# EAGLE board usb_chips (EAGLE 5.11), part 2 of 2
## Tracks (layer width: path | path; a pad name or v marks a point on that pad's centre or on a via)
3.3V  (via drill 0.6)
  Top 0.178: 52.92,24.64 TRANS3.12 52.95,24.64 53.47,24.64 53.72,24.38 53.72,23.75 v53.21,23.24 53.59,22.86 53.59,21.72 52.96,21.08 51.94,21.08 51.43,21.59 | PERIPH_XVER.12 39.61,24.65 40,24.26 40,23.11 39.5,22.61 v38.61,22.61 37.72,22.61 | JP12.2 46.48,23.11 49.15,23.11 49.53,22.73 49.53,21.59 50.04,21.08 50.93,21.08 51.43,21.59 | HOST1_CTL.P$23 48.37,40.41 48.39,40.39 48.39,40.13 v48.89,39.62 | 48.39,46.26 HOST1_CTL.P$2 48.37,47.35 48.51,47.5 v48.54,47.5 | v43.81,34.54 44.07,34.29 CLOSE_TO_PINS-2.2.2 | v34.04,22.61 35.05,21.59 36.96,21.59 37.72,22.35 37.72,22.61 | v27.69,23.37 26.42,24.64 26.02,24.64 HOST_XVER.12 | v22.86,22.35 23.75,21.46 24.51,21.46 24.89,21.84 24.89,23.11 24.77,23.24 HOST_XVER.14 | v28.96,50.42 28.45,49.91 25.53,49.91 24.77,50.67 24.77,52.71 24.38,53.09 23.62,53.09 23.5,52.96 22.61,52.96 21.84,53.72 21.84,55.37 22.1,55.63 22.48,55.63 22.99,56.13 22.99,56.9 22.35,57.53 21.84,57.53 21.08,56.77 21.08,53.09 v20.21,52.21 v20.19,52.21 20.08,52.21 19.81,52.48 18.31,52.48 17.78,51.94 17.78,48.51 18.41,47.88 18.41,47.37 17.65,46.61 17.65,45.21 17.14,44.7 16.76,44.7 16.38,44.32 14.48,44.32 13.59,45.21 13.59,46.99 15.49,48.9 v15.49,55.88 | PERIPH1_CTL.P$23 31.1,45.19 v31.62,45.72 32,46.1 34.8,46.1 v35.69,46.99 | 37.72,22.61 PERIPH_XVER.14 | 51.43,21.59 51.69,21.84 TRANS3.14 | v25.02,45.34 25.17,45.19 PERIPH1_CTL.P$2
  Bottom 0.178: 30.35,24.64 29.85,24.13 29.08,24.13 28.32,23.37 v27.69,23.37 27.69,22.99 26.92,22.22 24.89,22.22 24.51,21.84 23.37,21.84 v22.86,22.35 | 30.35,24.64 JP11.2 | 30.35,24.64 30.86,24.13 31.24,24.13 32.77,22.61 v34.04,22.61 | 15.37,64.35 C2.2 13.34,66.67 3.3V_REF.1 | 15.37,64.35 R14.1 | 14.35,56.39 14.86,56.9 14.86,60.58 16.51,62.23 16.51,63.21 15.37,64.35 | 14.87,55.87 14.35,56.39 | v25.02,45.34 22.99,47.37 22.99,51.69 22.1,52.58 20.57,52.58 v20.21,52.21 v20.19,52.21 | v15.49,55.88 15.48,55.87 14.87,55.87 | v28.96,50.42 29.85,49.53 29.85,47.5 v31.62,45.72 | v35.69,46.99 CLOSE_TO_PINS-1.1.2 CLOSE_TO_PINS-1.2.2 37.76,45.21 46.48,45.21 46.95,45.68 CLOSE_TO_PINS-2.1.2 48.39,46.74 | 48.39,46.74 48.39,40.13 v48.89,39.62 47.88,39.62 46.61,38.35 46.61,36.58 45.34,35.31 44.58,35.31 v43.81,34.54 46.74,31.62 46.74,27.94 JP12.2 44.2,24.51 43.81,24.13 42.8,24.13 41.91,23.24 40.13,23.24 39.5,22.61 v38.61,22.61 | 48.39,46.74 48.39,47.37 48.51,47.5 v48.54,47.5 | JP13.2 55.37,25.4 v53.21,23.24 | 14.35,56.39 14.3,56.44 3.3V_TOPROC.2 | 14.87,55.87 14.82,55.82 5V->3.3V.VOUT
5V  (via drill 0.6)
  Top 0.178: v44.58,15.49 43.81,16.26 42.8,16.26 42.42,16.64 41.15,16.64 40.89,16.89 v40.89,17.53 39.62,17.53 38.61,16.51 38.61,16 38.99,15.62 C13.2 | 5V_TOPROC.2 14.1,59.94 14.86,59.18 14.86,58.42 15.37,57.91 18.41,57.91 | 18.41,57.91 19.3,57.91 20.32,58.93 20.32,59.05 21.08,59.82 21.72,59.82 21.84,59.69 22.86,59.69 23.11,59.94 23.88,59.94 24.13,59.69 25.53,59.69 26.04,60.2 26.04,61.21 26.29,61.47 HOST1_VBUS.3 | v20.7,5.59 19.94,6.35 17.65,6.35 17.4,6.1 16.22,6.1 R1.2 | v16.26,13.84 16.26,9.53 15.75,9.02 15.75,7.37 16.13,6.98 R1.2 | R1.2 15.2,6.18 14.86,5.84 14.86,4.32 v14.35,3.81 | v8.51,42.16 7.49,43.18 3.05,43.18 1.4,41.53 1.4,6.35 v2.67,5.08 | v28.07,6.1 28.19,6.22 30.35,6.22 30.73,6.6 32.89,6.6 33.91,5.59 33.91,3.94 34.29,3.56 34.54,3.56 v35.18,2.92 | v46.61,6.35 46.99,6.73 48.89,6.73 49.4,6.22 50.67,6.22 v51.18,5.71 | HOST2_VBUS.3 37.46,59.82 37.72,59.56 38.35,59.56 38.99,58.93 41.4,58.93 v42.16,58.17 | v8,60.96 8.51,60.45 8.51,56.9 9.52,55.88 9.52,54.1 11.25,52.38 v11.35,52.38 | v14.86,65.15 10.41,65.15 v9.78,65.79 9.52,66.04 7.49,66.04 5V_SOURCE.1 | 18.41,57.91 16.51,56.01 16.51,55.25 15.88,54.61 15.88,48.77 14.86,47.75 v14.86,45.21
  Bottom 0.178: R2.2 27.73,6.44 v28.07,6.1 26.8,6.1 25.78,5.08 25.78,3.81 25.27,3.3 24.26,3.3 23.75,3.81 23.75,4.57 22.73,5.59 v20.7,5.59 | AP2146_3/4.IN 44.58,13.94 v44.58,15.49 45.08,16 45.34,16 46.1,16.76 46.86,16.76 47.24,16.38 48.13,16.38 49.28,17.53 50.04,17.53 50.55,17.02 50.55,16.26 50.29,16 50.29,9.4 50.67,9.02 50.67,6.22 v51.18,5.71 | C14.2 40.55,19.9 40.89,19.56 v40.89,17.53 | R4.2 47.88,7.62 v46.61,6.35 46.1,5.84 46.1,4.06 45.85,3.81 45.85,2.92 44.83,1.91 36.2,1.91 v35.18,2.92 35.18,3.3 35.94,4.06 35.94,4.95 37.08,6.1 37.59,6.1 37.85,6.35 37.85,7.4 R3.2 | AP2146_1/2.IN 15.24,21.55 C12.2 C11.2 15.02,18.38 15.11,18.29 15.62,18.29 16.64,17.27 17.91,17.27 19.05,16.13 19.05,14.86 18.03,13.84 v16.26,13.84 | v14.35,3.81 13.08,3.81 11.81,5.08 v2.67,5.08 | HOST1_VBUS.3 29.97,61.47 31.75,63.25 35.56,63.25 36.2,62.61 36.2,61.85 36.58,61.47 HOST2_VBUS.3 | v42.16,58.17 44.7,58.17 46.35,59.82 46.35,61.09 46.74,61.47 HOST3_VBUS.3 49.53,61.47 51.56,59.44 55.63,59.44 56.52,60.33 56.52,61.21 56.77,61.47 HOST4_VBUS.3 | R13.1 17.36,68.8 17.02,68.45 17.02,65.79 16.38,65.15 v14.86,65.15 | v9.78,65.79 10.29,65.79 10.79,65.28 C1.2 9.61,64.35 9.27,64.01 9.27,61.34 8.89,60.96 v8,60.96 8.51,60.45 8.51,58.67 9.02,58.17 12.32,58.17 13.34,59.18 5V_TOPROC.2 | 5V->3.3V.VIN 10.29,53.78 10.29,52.58 10.49,52.38 v11.35,52.38 | v8.51,42.16 11.81,42.16 v14.86,45.21
-RES1  (via drill 0.6)
  Top 0.178: PROC_INTERFACE.11 8.38,52.07 8.76,51.69 8.76,49.66 9.27,49.15 9.91,49.15 v10.16,48.9 | v30.89,37.62 30.84,37.62 28.07,40.39 PERIPH1_CTL.P$12
  Bottom 0.178: v10.16,48.9 10.54,49.28 15.11,49.28 17.91,52.07 17.91,53.72 18.29,54.1 19.05,54.1 19.69,53.47 22.35,53.47 22.73,53.09 24.38,53.09 24.77,52.71 24.77,47.88 26.8,45.85 26.8,43.05 28.83,41.02 28.83,40.13 30.48,38.48 30.48,38.02 v30.89,37.62
-RES2  (via drill 0.6)
  Top 0.178: HOST1_CTL.P$12 43.82,44.19 39.12,48.9 37.97,48.9 36.96,49.91 36.96,50.8 37.34,51.18 38.86,51.18 40.13,52.45 41.27,52.45 41.78,52.96 41.78,54.36 42.42,54.99 43.94,54.99 44.32,55.37 44.32,58.04 42.8,59.56 41.91,59.56 40.39,61.09 40.39,62.23 40.13,62.48 40.13,63.25 40.39,63.5 40.39,65.15 40.77,65.53 40.77,68.33 v40.13,68.96
  Bottom 0.178: PROC_INTERFACE.12 2.92,53.59 2.92,69.09 3.81,69.98 39.62,69.98 40.13,69.47 v40.13,68.96
-SS1  (via drill 0.6)
  Top 0.178: PERIPH1_CTL.P$14 29.07,40.91 31.24,38.74 32.13,38.74 32.38,38.48 32.77,38.48 33.02,38.23 v33.4,38.23
  Bottom 0.178: PROC_INTERFACE.9 8.25,53.34 8.25,52.45 10.67,50.04 14.86,50.04 17.14,52.32 17.14,53.98 18.03,54.86 19.3,54.86 19.94,54.23 22.61,54.23 22.99,53.85 24.64,53.85 25.53,52.96 25.53,48.13 27.56,46.1 27.56,43.31 29.59,41.28 29.59,40.39 31.24,38.74 32.13,38.74 32.38,38.48 33.15,38.48 v33.4,38.23
-SS2  (via drill 0.6)
  Top 0.178: HOST1_CTL.P$14 43.68,43.19 38.73,48.13 37.72,48.13 36.2,49.66 36.2,51.05 37.08,51.94 38.35,51.94 38.73,52.32 38.73,54.36 39.37,54.99 39.37,56.52 v40.89,58.04 | v41.02,62.87 42.16,64.01 v42.93,64.01
  Bottom 0.178: PROC_INTERFACE.14 2.54,51.44 2.54,69.21 3.68,70.36 40.39,70.36 41.02,69.72 41.02,68.33 40.77,68.07 40.77,64.64 41.4,64.01 v42.93,64.01 | v40.89,58.04 40.89,62.74 v41.02,62.87
GND  (via drill 0.6)
  Top 0.178: 18.41,64.77 3.3V_STATUS.C 17.94,64.55 16.38,62.99 | 18.41,64.77 19.43,64.77 v19.94,65.28 | v29.85,65.28 29.85,65.02 29.21,64.39 26.67,64.39 26.04,65.02 26.04,65.72 HOST1.GND | HOST2.GND 36.2,65.72 36.2,65.02 36.96,64.26 37.85,64.26 37.97,64.39 38.99,64.39 39.62,65.02 | v50.16,65.79 50.16,64.64 49.78,64.26 47.12,64.26 46.35,65.02 46.35,65.72 HOST3.GND | HOST4.GND 56.54,64.74 57.28,64.01 59.31,64.01 v59.56,64.26 | v18.16,8.64 18.25,8.64 PERIPH1_STATUS.C 19.56,9.27 19.81,9.02 19.84,9.04 v20.78,9.04 | TRANS3.PAD 51.18,25.65 TRANS3.6 51.18,27.94 v50.67,28.45 | C18.1 C19.1 53.38,40.13 52.45,40.13 51.94,39.62 v51.18,39.62 | v50.16,37.59 49.06,36.49 C20.1 48.39,35.47 CLOSE_TO_PINS-2.2.1 47.2,33.36 | HOST1_CTL.P$3 47.87,44.69 HOST1_CTL.P$33 46.37,43.19 HOST1_CTL.P$19 46.37,40.65 45.72,40.01 v44.7,40.01 | HOST1_CTL.P$3 47.88,46.25 | 47.2,33.36 46.86,33.02 44.07,33.02 40.89,36.2 v40.89,37.34 | GND_TOPROC.2 18.16,59.69 17.65,60.2 17.65,60.96 17.14,61.47 17.14,62.23 16.38,62.99 | 16.38,62.99 v15.62,62.99 | v16.26,57.02 15.24,57.02 14.48,56.26 14.48,54.74 13.84,54.1 v13.84,52.38 13.84,48.13 13.34,47.62 v10.16,47.62 | 31.37,53.09 C16.1 | 31.37,53.09 C17.1 | PERIPH1_CTL.P$3 27.57,44.69 PERIPH1_CTL.P$33 29.07,43.19 PERIPH1_CTL.P$19 32.12,43.19 v32.38,42.93 | HOST_XVER.PAD 24.26,25.65 HOST_XVER.6 24.26,28.09 v24.49,28.32 | v36.83,19.68 37.21,20.07 46.61,20.07 v48.64,22.1 | PERIPH_XVER.PAD 37.21,25.65 PERIPH_XVER.6 37.21,27.94 v37.59,28.32 | v16.64,7.75 16.64,12.47 v17.14,12.98 | v21.59,22.35 21.08,21.84 20.19,21.84 19.43,22.61 19.18,22.61 17.65,21.08 17.65,20.45 v18.29,19.81
  Top 0.178: v47.62,24.13 45.08,26.67 42.04,26.67 v41.91,26.8 | 5V_STATUS.C 17.56,68.99 17.02,68.45 | 17.02,68.45 17.02,66.17 18.41,64.77 | 17.02,68.45 16.51,67.94 3.3V_REF.2 12.7,66.04 11.05,66.04 9.14,67.94 5V_SOURCE.2 | v31.37,51.56 31.37,53.09 | HOST1_CTL.P$3 47.87,46.62 47.75,46.74 47.75,47.62 47.37,48.01 v47.37,48.64 | PERIPH3_STATUS.C 40.13,12.06 40.51,12.45 40.51,13.46 | v40.51,13.59 40.51,13.46 | 40.51,13.46 40.17,13.12 C13.1 | v37.46,15.75 34.92,13.21 PERIPH2.GND | 46.48,17.27 46.48,18.29 46.1,18.67 42.54,18.67 v42.04,18.16 | 46.48,17.27 v46.48,15.88 | C10.1 56.01,12.79 56.01,11.81 55.75,11.56 55.5,11.56 55.18,11.24 PERIPH4.GND | PERIPH3.GND 46.73,8.89 47.37,8.89 48.93,7.33 PERIPH4_STATUS.C | 46.48,17.27 v47.75,17.27 | PERIPH1.GND 24.77,12.19 27.18,14.61 28.7,14.61 29.08,14.22 | 29.08,14.22 29.08,12.99 C5.1 29.21,12.87 29.21,11.94 29.72,11.43 PERIPH2_STATUS.C | 29.08,14.22 29.59,14.22 v29.95,14.58 | 39.62,65.02 39.62,63.75 39.37,63.5 39.37,62.23 39.62,61.98 39.62,60.35 v39.22,59.94 | 39.62,65.02 39.62,66.06 v39.6,66.09 | 47.2,33.36 47.85,32.72 v48.08,32.72
  Bottom 0.178: v15.62,62.99 15.28,62.65 C2.1 C1.1 | v19.94,65.28 21.72,67.06 28.07,67.06 v29.85,65.28 31.62,67.06 38.63,67.06 v39.6,66.09 39.62,66.06 39.62,65.28 41.27,63.63 41.91,63.63 42.29,63.25 42.8,63.25 42.93,63.12 43.81,63.12 44.58,63.88 48.26,63.88 v50.16,65.79 51.43,67.06 58.55,67.06 59.82,65.79 59.82,64.52 v59.56,64.26 | C3.1 17.57,9.23 v18.16,8.64 19.69,7.11 C4.1 | C7.1 42.54,8.64 43.18,8.64 PERIPH3.GND 45.08,13.59 45.31,13.81 AP2146_3/4.GND 45.72,15.11 v46.48,15.88 | v50.16,37.59 50.16,38.61 v51.18,39.62 | CLOSE_TO_PINS-2.1.1 45.25,48.17 45.72,48.64 v47.37,48.64 | 5V->3.3V.GND 13.34,53.85 13.84,53.34 v13.84,52.38 | v16.26,57.02 16.76,57.02 17.65,57.91 17.65,59.18 18.16,59.69 GND_TOPROC.2 | AP2146_1/2.GND 16.51,21.55 C12.1 | C12.1 C11.1 16.73,18.2 17.27,17.65 18.03,17.65 19.43,16.26 19.43,14.48 17.93,12.98 v17.14,12.98 | C3.1 17.65,10.25 | v16.64,7.75 16.89,8 16.89,9.49 C3.1 | C14.1 37.81,18.2 37.72,18.29 37.72,18.8 v36.83,19.68 | v48.64,22.1 48.64,24.13 | 48.64,24.13 48.64,26.42 v50.67,28.45 50.16,28.96 50.16,29.72 48.08,31.8 v48.08,32.72 | v21.59,22.35 22.73,23.5 22.73,24.89 23.24,25.4 24,25.4 24.26,25.65 24.26,27.43 24.51,27.69 24.51,28.3 v24.49,28.32 | v18.29,19.81 17.78,20.32 17.78,21.08 17.53,21.34 C12.1 | v44.7,40.01 42.04,37.34 v40.89,37.34 37.72,40.51 CLOSE_TO_PINS-1.2.1 CLOSE_TO_PINS-1.1.1 35.65,43.43 34.42,43.43 | v41.91,26.8 41.53,27.18 39.75,27.18 39.5,27.43 37.85,27.43 37.59,27.69 v37.59,28.32 | 48.64,24.13 v47.62,24.13 | v32.38,42.93 32.89,43.43 34.42,43.43 | 34.42,43.43 34.04,43.82 34.04,45.47 33.62,45.89 C15.1 33.62,51.47 33.53,51.56
  Bottom 0.178: 33.53,51.56 37.21,51.56 38.23,52.58 38.23,54.86 38.99,55.63 38.99,56.64 39.62,57.28 39.62,59.54 v39.22,59.94 | 33.53,51.56 v31.37,51.56 | C14.1 38.73,17.02 v37.46,15.75 37.08,15.37 34.29,15.37 33.91,15.75 33.4,15.75 33.02,15.37 30.73,15.37 v29.95,14.58 | C14.1 39.84,18.2 40,18.03 40,17.14 40.51,16.64 | 40.51,16.64 v40.51,13.59 39.97,13.04 C8.1 | v42.04,18.16 42.04,17.27 41.4,16.64 40.51,16.64 | v47.75,17.27 48.51,17.27 49.15,17.91 50.16,17.91 50.93,17.14 50.93,16.13 50.67,15.88 50.67,9.53 51.05,9.14 51.05,8.64 51.43,8.26 52.67,8.26 C9.1 53.68,8.22 54.1,8.64 54.1,9.46 PERIPH4.GND | C6.1 33.49,8.47 33.91,8.89 33.91,9.52 PERIPH2.GND | v10.16,47.62 10.28,47.75 5V->3.3V.GND_TAB | PERIPH1.GND 23.27,9.04 v20.78,9.04
GPX1  (via drill 0.6)
  Top 0.178: PERIPH1_CTL.P$17 31.09,42.19 31.24,42.04 v31.24,41.28
  Bottom 0.178: PROC_INTERFACE.6 5.59,58.55 7.62,58.55 8.13,58.04 8.13,56.77 9.14,55.75 9.14,53.98 9.4,53.72 9.4,52.83 11.05,51.18 14.48,51.18 16,52.71 16,54.61 17.4,56.01 19.81,56.01 20.45,55.37 22.99,55.37 23.37,54.99 25.02,54.99 26.67,53.34 26.67,48.64 28.7,46.61 28.7,43.69 31.12,41.28 v31.24,41.28
GPX2  (via drill 0.6)
  Top 0.178: HOST1_CTL.P$17 45.37,41.43 45.21,41.28 44.32,41.28 42.16,39.12 40.26,39.12 39.62,38.48 38.99,38.48 38.35,37.85 38.35,37.08 37.85,36.58 33.66,36.58 33.15,36.07 25.53,36.07 21.08,31.62 17.53,31.62 16.89,32.26 16.89,33.53 16.13,34.29 13.34,34.29 11.3,36.32 11.3,42.42 v10.16,43.56
  Bottom 0.178: v10.16,43.56 9.27,44.45 PROC_INTERFACE.17
HOST4_D+  (via drill 0.6)
  Top 0.178: v55.63,64.14 55.24,64.52 HOST4.D+ | v10.16,4.19 10.16,4.83 9.91,5.08 5.71,5.08 PROC_INTERFACE.47
  Bottom 0.178: PASSTHRU_OR_LOOPBACK.4 56.01,17.78 57.28,19.05 59.56,19.05 60.07,19.56 | 60.07,19.56 60.07,62.48 58.93,63.63 56.13,63.63 v55.63,64.14 | 60.07,19.56 60.07,14.22 60.45,13.84 60.45,2.92 58.67,1.14 14.35,1.14 12.57,2.92 11.43,2.92 v10.16,4.19
HOST4_D-  (via drill 0.6)
  Top 0.178: 60.07,17.78 58.8,16.51 56.52,16.51 56.52,16.46 PASSTHRU_OR_LOOPBACK.3 | 60.07,17.78 60.07,62.74 59.56,63.25 55.24,63.25 54.59,63.9 HOST4.D- | 60.07,17.78 60.07,14.22 60.45,13.84 60.45,2.92 58.67,1.14 14.35,1.14 11.3,4.19 v11.3,6.35
  Bottom 0.178: PROC_INTERFACE.48 v11.3,6.35
HOST_XVER_D+  (via drill 0.6)
  Top 0.178: v18.16,26.29 16.26,24.38 14.1,24.38 13.34,25.15 v13.34,26.04 | v35.31,64.14 34.92,64.52 HOST2.D+ | v21.46,58.93 20.83,58.93 19.43,57.53 18.54,57.53 16.89,55.88 16.89,55.12 16.26,54.48 16.26,48.64 15.75,48.13 v15.75,46.48 | v10.16,29.84 10.16,41.02 v9.91,41.28 | v27.3,25.15 HOST_XVER.11
  Bottom 0.178: v27.3,25.15 27.3,26.16 26.29,27.18 26.04,27.18 25.78,27.43 25.4,27.43 25.15,27.69 25.15,27.81 25.27,27.94 25.27,28.7 24.77,29.21 24.26,29.21 23.5,28.45 23.07,28.45 R20.1 22.39,28.36 20.7,26.67 18.54,26.67 v18.16,26.29 | v13.34,26.04 11.05,28.32 11.05,28.96 v10.16,29.84 | v21.46,58.93 22.23,59.69 22.86,59.69 23.11,59.94 23.88,59.94 24.13,59.69 25.53,59.69 26.04,60.2 26.04,62.99 26.8,63.75 34.92,63.75 v35.31,64.14 34.92,64.52 | v9.91,41.28 12.83,41.28 15.75,44.2 v15.75,46.48
HOST_XVER_D-  (via drill 0.6)
  Top 0.178: HOST_XVER.10 26.54,25.65 26.8,25.91 27.18,25.91 v27.94,26.67 28.45,26.16 28.45,24.89 29.21,24.13 31.24,24.13 32.13,25.02 32.13,25.91 32.64,26.42 32.64,27.3 32.89,27.56 32.89,28.96 33.4,29.46 34.16,29.46 34.67,29.97 34.67,32.08 v35.33,32.74 | HOST2.D- 34.27,63.77 34.8,63.25 36.2,63.25 36.45,63.5 v38.48,63.5 | v36.58,38.35 37.34,38.35 38.61,39.62 39.24,39.62 39.88,40.26 41.66,40.26 43.56,42.16 43.56,42.8 40.26,46.1 v39.62,46.1
  Bottom 0.178: v27.94,26.67 27.18,27.43 26.54,27.43 26.54,28.13 R19.1 | v38.48,63.5 40,61.98 40,57.15 39.37,56.52 39.37,55.5 38.61,54.74 38.61,52.45 36.96,50.8 36.96,49.91 39.62,47.24 v39.62,46.1 | v35.33,32.74 35.53,32.74 36.58,33.78 v36.58,38.35
HOST_XVER_VPU  (via drill 0.6)
  Top 0.178: HOST_XVER.13 25.26,22.11 25.78,21.59 31.88,21.59 32.38,22.1 v32.38,24.13 | SPEED_JMPR1.2 30.1,30.86 30.35,30.61 30.35,29.84 31.12,29.08 32,29.08 32.26,28.83 32.26,27.18 v31.75,26.67
  Bottom 0.178: v32.38,24.13 32.38,25.27 32.13,25.53 32.13,26.29 v31.75,26.67
I/O_EN1  (via drill 0.6)
  Top 0.178: PROC_INTERFACE.26 1.78,31.62 1.78,10.92 2.54,10.16 8.51,10.16 9.78,8.89 10.29,8.89 11.05,9.65 11.05,11.68 16.89,17.53 16.89,21.34 19.43,23.88 21.46,23.88 21.46,23.82 v21.72,23.57
  Bottom 0.178: I/O_EN_HOST.G 22.48,26.67 21.72,25.91 v21.72,23.57
I/O_EN2  (via drill 0.6)
  Top 0.178: v9.14,18.8 9.14,20.95 8.76,21.34 8.76,23.5 9.14,23.88 v9.14,24.51
  Bottom 0.178: I/O_EN_PERIPH.G 36.52,23.69 34.42,21.59 32.64,21.59 32.38,21.34 21.59,21.34 19.94,19.68 19.94,14.22 17.91,12.19 16.38,12.19 13.84,14.73 12.83,14.73 12.32,15.24 12.32,17.78 11.81,18.29 11.3,18.29 11.05,18.54 9.4,18.54 v9.14,18.8 | PROC_INTERFACE.34 5.51,23.06 7.7,23.06 v9.14,24.51
I/O_EN3  (via drill 0.6)
  Top 0.178: v14.35,8.38 14.86,8.89 14.86,12.19 v14.48,12.57
  Bottom 0.178: v14.35,8.38 13.84,8.38 12.57,7.11 12.57,6.6 13.34,5.84 14.1,5.84 18.41,1.52 58.55,1.52 59.82,2.79 59.82,4.57 58.67,5.71 56.64,5.71 56.26,6.1 56.26,14.48 56.52,14.73 56.52,16 56.01,16.51 54.48,16.51 53.97,17.02 53.97,18.92 53.47,19.43 50.67,19.43 49.66,20.45 49.66,22.35 49.4,22.61 49.4,26.42 49.66,26.67 I/O_EN_SNOOP.G | PROC_INTERFACE.42 7.49,13.46 13.59,13.46 v14.48,12.57
INT1  (via drill 0.6)
  Top 0.178: PROC_INTERFACE.5 7.11,59.69 8.13,58.67 8.13,56.77 9.14,55.75 9.14,53.98 10.54,52.58 10.54,51.94 10.92,51.56 12.17,51.56 v12.57,51.97 | PERIPH1_CTL.P$18 31.48,42.69 v32.51,41.66
  Bottom 0.178: v32.51,41.66 32,42.16 30.73,42.16 29.08,43.82 29.08,46.86 27.05,48.9 27.05,53.47 25.15,55.37 23.5,55.37 23.11,55.75 20.57,55.75 19.94,56.39 17.14,56.39 15.62,54.86 15.62,52.83 14.35,51.56 12.98,51.56 v12.57,51.97
INT2
  Top 0.178: HOST1_CTL.P$18 45.87,41.17 45.59,40.89 44.45,40.89 42.29,38.74 40.39,38.74 39.75,38.1 39.12,38.1 38.73,37.72 38.73,36.96 37.97,36.2 33.78,36.2 33.27,35.69 25.65,35.69 21.21,31.24 17.27,31.24 16.51,32 16.51,33.4 16,33.91 13.21,33.91 10.92,36.2 10.92,41.78 10.29,42.42 9.91,42.42 9.14,43.18 9.14,44.7 8.13,45.72 5.71,45.72 PROC_INTERFACE.18
MISO1  (via drill 0.6)
  Top 0.178: v32.77,39.5 32.38,39.12 31.37,39.12 29.57,40.91 PERIPH1_CTL.P$15
  Bottom 0.178: PROC_INTERFACE.8 5.71,55.88 8,55.88 8.38,55.5 8.38,53.72 8.64,53.47 8.64,52.58 10.79,50.42 14.73,50.42 16.76,52.45 16.76,54.1 17.91,55.25 19.43,55.25 20.07,54.61 22.73,54.61 23.11,54.23 24.77,54.23 25.91,53.09 25.91,48.26 27.94,46.23 27.94,43.43 29.97,41.4 29.97,40.51 31.37,39.12 32.38,39.12 v32.77,39.5
MISO2  (via drill 0.6)
  Top 0.178: HOST1_CTL.P$15 44.22,42.69 44.07,42.55 44.07,42.04 41.91,39.88 40,39.88 39.37,39.24 38.73,39.24 37.59,38.1 37.59,37.59 37.34,37.34 33.4,37.34 32.89,36.83 25.27,36.83 23.6,35.15 20.85,35.15 19.99,34.29 19.99,32.64 19.74,32.38 18.03,32.38 17.65,32.77 17.65,33.78 16.38,35.05 13.59,35.05 12.07,36.58 v12.07,45.59
  Bottom 0.178: v12.07,45.59 10.54,45.59 9.14,46.99 PROC_INTERFACE.15
MOSI1  (via drill 0.6)
  Top 0.178: v31.62,40.13 30.86,40.13 30.07,40.92 PERIPH1_CTL.P$16
  Bottom 0.178: PROC_INTERFACE.7 7.24,57.15 8.76,55.63 8.76,53.85 9.02,53.59 9.02,52.71 10.92,50.8 14.61,50.8 16.38,52.58 16.38,54.36 17.65,55.63 19.56,55.63 20.19,54.99 22.86,54.99 23.24,54.61 24.89,54.61 26.29,53.21 26.29,48.39 28.32,46.36 28.32,43.56 30.35,41.53 30.35,40.64 30.86,40.13 v31.62,40.13
MOSI2  (via drill 0.6)
  Top 0.178: HOST1_CTL.P$16 44.82,41.77 44.7,41.66 44.2,41.66 42.04,39.5 40.13,39.5 39.5,38.86 38.86,38.86 37.97,37.97 37.97,37.21 37.72,36.96 33.53,36.96 33.02,36.45 25.4,36.45 23.72,34.77 21.01,34.77 20.4,34.16 20.4,32.38 20.02,32 17.65,32 17.27,32.38 17.27,33.66 16.26,34.67 13.46,34.67 11.68,36.45 11.68,43.82 v11.05,44.45
  Bottom 0.178: v11.05,44.45 9.65,45.85 5.59,45.85 PROC_INTERFACE.16
N$1  (via drill 0.6)
  Top 0.178: PERIPH1_CTL.P$21 33.28,44.19 34.54,42.93 34.54,41.91 v33.27,40.64 | v23.5,58.93 23.88,59.31 25.65,59.31 26.04,59.69 27.81,59.69 28.83,60.71 29.81,60.71 R9.1 | v22.1,56.64 21.46,56.01 21.46,53.59 22.48,52.58 23.7,52.58 v23.98,52.3
  Bottom 0.178: v33.27,40.64 33.78,40.13 33.78,39.24 34.54,38.48 34.54,38.1 33.78,37.34 33.4,37.34 32.89,36.83 30.48,36.83 30.1,37.21 30.1,38.35 28.45,40.01 28.45,40.89 26.42,42.93 26.42,45.72 24.38,47.75 24.38,51.89 v23.98,52.3 | v22.1,56.64 21.59,57.15 21.59,57.91 22.23,58.55 23.11,58.55 v23.5,58.93
N$2  (via drill 0.6)
  Top 0.178: v33.66,42.42 33.66,42.93 32.77,43.82 31.88,43.82 31.75,43.69 PERIPH1_CTL.P$20 | R10.1 19.9,54.36 18.92,54.36 18.69,54.13 v18.69,53.26
  Bottom 0.178: v33.66,42.42 33.66,41.78 34.29,41.15 34.29,39.24 34.92,38.61 34.92,37.97 33.91,36.96 33.53,36.96 33.02,36.45 30.23,36.45 29.72,36.96 29.72,38.23 28.07,39.88 28.07,40.77 26.04,42.8 26.04,45.47 23.37,48.13 23.37,51.82 22.1,53.09 18.92,53.09 18.75,53.26 v18.69,53.26
N$5  (via drill 0.6)
  Top 0.178: TRANS3.11 53.72,25.15 54.1,24.77 54.1,21.72 53.09,20.7 52.58,20.7 52.2,20.32 v51.31,20.32 50.55,19.56 50.55,18.8 46.99,15.24 46.99,14.35 v48.13,13.21 | 59.56,33.02 59.56,21.72 59.05,21.21 v56.01,21.21 | 59.56,33.02 59.56,59.18 59.05,59.69 51.69,59.69 50.04,61.34 50.04,63.37 49.53,63.88 48.77,63.88 48.51,63.63 45.72,63.63 45.08,64.26 HOST3.D+ | 59.56,33.02 v58.55,33.02
  Bottom 0.178: v58.55,33.02 58.04,33.53 49.91,33.53 49.4,34.04 49.4,34.54 48.39,35.56 46.35,35.56 46.01,35.22 R23.1 | v56.01,21.21 55.12,20.32 v51.31,20.32 | PERIPH3.D+ 46.07,9.53 46.1,9.53 46.1,12.06 46.74,12.7 47.62,12.7 v48.13,13.21
N$6  (via drill 0.6)
  Top 0.178: PERIPH3.D- v46.48,7.94 | TRANS3.10 53.85,25.65 54.48,25.02 54.48,21.59 53.21,20.32 52.7,20.32 51.94,19.56 | 51.94,19.56 v56.52,19.56 | v49.66,16.64 49.66,17.27 51.94,19.56 | HOST3.D- 44.43,64.28 45.47,63.25 48.89,63.25 v49.15,62.99
  Bottom 0.178: 59.56,34.29 59.56,19.81 59.31,19.56 v56.52,19.56 | 59.56,34.29 59.56,62.48 58.8,63.25 49.4,63.25 v49.15,62.99 | R24.1 50.58,35.39 51.94,34.04 59.31,34.04 59.56,34.29 | v46.48,7.94 46.48,8.64 46.74,8.89 49.28,8.89 49.91,9.53 49.91,16.38 v49.66,16.64
N$9  (via drill 0.6)
  Top 0.178: v58.8,6.86 58.48,6.54 PERIPH4.D- | v59.56,13.46 59.56,13.51 PASSTHRU_OR_LOOPBACK.5
  Bottom 0.178: v58.8,6.86 60.07,8.13 60.07,12.95 v59.56,13.46
N$10  (via drill 0.6)
  Top 0.178: v58.55,8.64 55.28,8.64 PERIPH4.D+
  Bottom 0.178: v58.55,8.64 59.69,9.78 59.69,12.06 58.67,13.08 58.67,14.22 59.05,14.61 59.05,16.56 PASSTHRU_OR_LOOPBACK.6
N$11  (via drill 0.6)
  Top 0.178: PERIPH2.D- 33.72,6.54 31.37,8.89 v31.12,8.89 | PERIPH2_OR_HOST4.5 34.04,16.51 33.66,16.13 v33.66,14.86
  Bottom 0.178: v31.12,8.89 30.48,8.89 30.23,9.14 30.23,13.33 31.12,14.22 31.12,14.61 31.5,14.99 33.53,14.99 v33.66,14.86
N$12
  Top 0.178: PERIPH2.D+ 34.92,8.89 33.91,9.91 33.91,11.3 34.54,11.94 34.54,13.33 36.07,14.86 36.07,17.91 PERIPH2_OR_HOST4.6
N$13  (via drill 0.6)
  Top 0.178: PERIPH2_OR_HOST4.3 32.89,16.51 33.66,17.27 33.66,19.56 34.67,20.57 41.53,20.57 42.04,21.08 42.04,22.86 | PERIPH_XVER.10 40,25.65 40.77,24.89 40.77,23.62 41.53,22.86 42.04,22.86 | 42.04,22.86 42.54,23.37 42.54,24.77 41.02,26.29 41.02,27.18 41.91,28.07 v41.91,28.19
  Bottom 0.178: R22.1 43.81,29.46 43.56,29.21 42.8,29.21 41.91,28.32 v41.91,28.19
N$14  (via drill 0.6)
  Top 0.178: PERIPH2_OR_HOST4.4 34.42,21.08 38.99,21.08 40.39,22.48 | 40.39,22.48 40.39,24.77 40,25.15 PERIPH_XVER.11 | 40.39,22.48 41.02,21.84 v41.15,21.84 | v46.74,26.16 46.74,26.54 46.1,27.18 46.1,28.83 v45.85,29.08
  Bottom 0.178: v41.15,21.84 42.54,21.84 42.8,21.59 45.85,21.59 46.48,22.22 46.48,24.77 46.74,25.02 v46.74,26.16 | v45.85,29.08 45.85,31.88 44.2,33.53 42.04,33.53 41.62,33.95 R21.1
N$15  (via drill 0.6)
  Top 0.178: v36.93,18.29 36.93,18.52 37.97,19.56 47.37,19.56 v48.13,20.32 | PERIPH2_OR_HOST4.2 28.57,17.78 v26.16,17.78
  Bottom 0.178: PERIPH2_OR_HOST4.2 30.35,19.05 31.42,17.98 36.63,17.98 v36.93,18.29 | v26.16,17.78 22.23,17.78 21.97,18.03 PERIPH1_OR_HOST4.2 | v48.13,20.32 48.39,20.32 49.66,19.05 51.49,19.05 PASSTHRU_OR_LOOPBACK.2
N$16  (via drill 0.6)
  Top 0.178: v36.96,17.02 37.21,17.02 39.24,19.05 v48.26,19.05 | PERIPH2_OR_HOST4.1 28.57,16.51 27.43,15.37 26.92,15.37 26.04,14.48 25.02,14.48 24.13,15.37 23.11,15.37 PERIPH1_OR_HOST4.1
  Bottom 0.178: PERIPH2_OR_HOST4.1 30.73,16.51 31.8,17.58 36.4,17.58 v36.96,17.02 | v48.26,19.05 49.15,19.05 49.53,18.67 50.8,18.67 51.69,17.78 51.69,16.26 51.74,16.26 PASSTHRU_OR_LOOPBACK.1
N$17
  Top 0.178: HOST1_CTL.P$21 47.37,39.62 47.12,39.37 47.12,36.83 46.61,36.32 R11.1
N$18  (via drill 0.6)
  Top 0.178: PERIPH1_OR_HOST4.4 26.16,20.7 32.51,20.7 33.15,21.34 33.15,23.24 33.66,23.75 33.66,24.51 32.89,25.27 32.89,25.65 33.4,26.16 33.4,27.05 33.66,27.3 33.66,28.45 33.91,28.7 36.83,28.7 37.72,29.59 37.72,32.59 v37.87,32.74 | v42.04,36.32 R11.2
  Bottom 0.178: v42.04,36.32 38.99,36.32 38.48,35.81 38.48,33.02 38.2,32.74 v37.87,32.74
N$19  (via drill 0.6)
  Top 0.178: v26.29,23.11 26.54,23.11 27.3,22.35 28.19,22.35 28.7,22.86 JP11.1 | HOST_XVER.15 24.26,22.99 v24,22.73
  Bottom 0.178: v24,22.73 24.51,23.24 | 24.51,23.24 24.64,23.11 v26.29,23.11 | 24.51,23.24 24.51,23.62 24.26,23.88 I/O_EN_HOST.D
N$20
  Bottom 0.178: PERIPH1_OR_HOST4.5 27.05,15.49 26.54,14.99 26.54,13.33 27.05,12.83 28.32,12.83 29.46,11.68 29.46,9.4 29.08,9.02 26.54,9.02 25.91,8.38 25.91,7.68 PERIPH1.D-
N$21  (via drill 0.6)
  Top 0.178: PERIPH1.D+ 24.92,8.54 25.78,9.4 25.78,11.94 v27.56,13.72
  Bottom 0.178: v27.56,13.72 27.56,15.49 28.19,16.13 28.19,17.91 PERIPH1_OR_HOST4.6
N$22  (via drill 0.6)
  Top 0.178: PERIPH_XVER.13 38.96,23.9 v39.12,23.75 | SPEED_JMPR2.2 40,30.48 40.26,30.23 40.26,29.46 41.02,28.7 41.02,28.07 40.64,27.69 40.64,26.42 40.39,26.16 40.39,25.91 41.15,25.15 41.15,24.64 v41.66,24.13
  Bottom 0.178: v39.12,23.75 41.27,23.75 v41.66,24.13
N$23
  Top 0.178: HOST1.VBUS 23.46,62.77 HOST1_VBUS.2
N$24
  Top 0.178: HOST2.VBUS 33.62,62.77 HOST2_VBUS.2
N$25
  Top 0.178: HOST3.VBUS 43.78,62.77 HOST3_VBUS.2
N$26
  Top 0.178: HOST4.VBUS 53.97,65.72 53.97,63.5 55.24,62.23 HOST4_VBUS.2
N$27  (via drill 0.6)
  Top 0.178: PERIPH_XVER.15 37.21,23.12 36.58,22.48 v36.45,22.48
  Bottom 0.178: JP12.1 40.26,22.86 39.12,21.72 37.46,21.72 | 37.46,21.72 37.21,21.72 v36.45,22.48 | 37.46,21.72 I/O_EN_PERIPH.D
N$28
  Bottom 0.178: I/O_EN_HOST.S 25.21,25.72 26.67,24.26 27.81,24.26 28.45,24.89 28.45,26.04 29.08,26.67 29.59,26.67 30.35,27.43 JP11.3
N$29
  Bottom 0.178: JP12.3 44.2,27.05 43.56,26.42 42.67,26.42 41.15,24.89 38.73,24.89 38.48,25.15 38.48,26.6 I/O_EN_PERIPH.S
N$30
  Bottom 0.178: JP13.3 56.52,26.67 I/O_EN_SNOOP.S
N$31  (via drill 0.6)
  Top 0.178: v17.91,16 18.41,15.49 18.41,14.73 v20.57,12.57 | v13.34,22.48 13.34,20.95 13.46,20.83 v13.46,18.29
  Bottom 0.178: v17.91,16 R15.2 15.88,16.17 15.88,17.27 15.37,17.78 13.97,17.78 v13.46,18.29 | v20.57,12.57 19.27,11.26 C3.2 19.27,8.8 19.81,8.26 21.59,8.26 21.84,8 21.84,7.2 C4.2 22.73,7.11 23.37,6.48 23.37,5.94 PERIPH1.VBUS | AP2146_1/2.OUT1 13.97,23.11 v13.34,22.48
N$32  (via drill 0.6)
  Top 0.178: v36.45,6.6 35.94,7.11 35.94,11.05 35.43,11.56 35.43,12.47 v37.46,14.5 | v22.23,13.46 20.57,13.46 18.92,15.11 v18.92,18.03 | C5.2 30.73,13.04 30.73,13.84 31.12,14.22 | v23.88,14.48 24.26,14.1 26.16,14.1 27.05,14.99 27.69,14.99 28.07,15.37 30.61,15.37 31.12,14.86 31.12,14.22 | 31.12,14.22 32.38,14.22 v32.51,14.1
  Bottom 0.178: C6.2 32.7,6.77 PERIPH2.VBUS 36.45,6.06 v36.45,6.6 | v23.88,14.48 23.91,14.44 R16.2 22.99,12.95 22.48,13.46 v22.23,13.46 | v18.92,18.03 19.43,18.54 19.43,21.59 17.91,23.11 17.91,23.84 AP2146_1/2.OUT2 | v32.51,14.1 32.64,13.97 36.93,13.97 v37.46,14.5
N$33  (via drill 0.6)
  Top 0.178: v39.5,16.26 42.29,16.26 43.18,15.37 v43.31,15.37
  Bottom 0.178: v43.31,15.37 43.31,13.94 AP2146_3/4.OUT1 42.26,13.81 42.04,13.59 42.04,13.08 40.51,11.56 40.51,9.4 41.4,8.51 41.4,6.98 41.62,6.77 C7.2 43.78,6.77 44.07,6.48 44.07,5.56 PERIPH3.VBUS | v39.5,16.26 38.99,15.75 C8.2 | C8.2 38.91,14.74 | R17.2 36.97,12.83 38.89,14.74 C8.2
N$34  (via drill 0.6)
  Top 0.178: v48.01,15.11 50.13,15.11 R18.2 51.22,15.07 53.47,12.83 C10.2 54.23,12.79 54.23,11.68 54.1,11.56 54.1,5.62 PERIPH4.VBUS
  Bottom 0.178: C9.2 53.81,6.52 54.23,6.1 54.23,5.49 PERIPH4.VBUS | AP2146_3/4.OUT2 47.46,13.81 47.75,14.1 47.75,14.86 v48.01,15.11
N$35
  Top 0.178: PERIPH1_CTL.P$26 29.57,49.26 29.59,49.28 29.34,49.53 25.27,49.53 23.37,51.44 XCEIVER1_GPIOS.2
N$36
  Top 0.178: PERIPH1_CTL.P$27 29.08,46.2 29.08,48.64 28.83,48.9 XCEIVER1_GPIOS.4
N$37
  Top 0.178: PERIPH1_CTL.P$28 28.57,48.26 28.32,48.51 22.73,48.51 21.46,47.24 XCEIVER1_GPIOS.6
N$38
  Top 0.178: PERIPH1_CTL.P$29 28.07,47.75 27.81,48.01 22.99,48.01 22.61,47.62 22.61,45.85 21.46,44.7 XCEIVER1_GPIOS.8
N$39
  Top 0.178: PERIPH1_CTL.P$30 27.57,47.23 27.3,47.5 23.24,47.5 22.99,47.24 22.99,45.21 22.61,44.83 22.61,43.43 21.46,42.29 XCEIVER1_GPIOS.10
N$40
  Top 0.178: PERIPH1_CTL.P$31 27.07,46.72 26.8,46.99 23.75,46.99 23.37,46.61 23.37,45.09 22.99,44.7 22.99,43.31 22.61,42.93 22.61,40.89 21.46,39.75 XCEIVER1_GPIOS.12
N$41
  Top 0.178: PERIPH1_CTL.P$32 26.57,46.45 26.42,46.61 24.13,46.61 23.75,46.23 23.75,44.96 23.37,44.58 23.37,43.18 22.99,42.8 22.99,40.39 22.61,40.01 22.61,38.35 21.46,37.21 XCEIVER1_GPIOS.14
N$42  (via drill 0.6)
  Top 0.178: v28.19,37.59 25.53,37.59 24.51,36.58 23.5,36.58 22.99,37.08 22.99,39.62 23.37,40.01 23.37,42.67 23.75,43.05 23.75,44.45 24.13,44.83 24.13,45.85 24.51,46.23 25.78,46.23 26.04,45.97 26.04,45.85 26.02,45.85 PERIPH1_CTL.P$1
  Bottom 0.178: v28.19,37.59 28.19,35.31 27.43,34.54 23.37,34.54 22.48,33.66 XCEIVER1_GPIOS.16
N$43  (via drill 0.6)
  Top 0.178: v24.64,44.2 v24.64,44.19 PERIPH1_CTL.P$4
  Bottom 0.178: v24.64,44.2 22.61,46.23 22.61,49.91 22.23,50.29 20.19,50.29 19.05,51.44 XCEIVER1_GPIOS.1
N$44  (via drill 0.6)
  Top 0.178: PERIPH1_CTL.P$5 25.28,43.69 25.02,43.43 24.77,43.43 24,42.67 v24.26,42.42
  Bottom 0.178: v24.26,42.42 23.5,43.18 23.5,44.2 22.61,45.09 21.21,45.09 20.32,45.97 20.32,47.62 19.05,48.9 XCEIVER1_GPIOS.3
N$45  (via drill 0.6)
  Top 0.178: PERIPH1_CTL.P$6 25.29,43.19 25.15,43.05 25.15,42.04 v24.26,41.15
  Bottom 0.178: XCEIVER1_GPIOS.5 19.05,46.36 20.32,45.09 20.32,43.43 20.96,42.8 20.96,42.77 22.63,42.77 v24.26,41.15
N$46  (via drill 0.6)
  Top 0.178: PERIPH1_CTL.P$7 25.55,42.69 25.53,42.67 25.53,41.91 25.15,41.53 25.15,40.51 24.51,39.88 v24.13,39.88
  Bottom 0.178: v24.13,39.88 24,39.88 22.73,41.15 22.73,41.91 22.28,42.37 20.37,42.37 XCEIVER1_GPIOS.7
N$47  (via drill 0.6)
  Top 0.178: PERIPH1_CTL.P$8 26.02,41.9 25.53,41.4 25.53,40.39 25.02,39.88 25.02,39.37 v24.26,38.61
  Bottom 0.178: XCEIVER1_GPIOS.9 19.96,40.23 22.63,40.23 v24.26,38.61
N$48  (via drill 0.6)
  Top 0.178: PERIPH1_CTL.P$9 26.28,41.64 25.91,41.28 25.91,40.13 25.4,39.62 25.4,38.53 24.26,37.39 v24,37.39
  Bottom 0.178: v24,37.39 23.37,38.02 23.37,38.74 22.28,39.83 20.02,39.83 XCEIVER1_GPIOS.11
N$49  (via drill 0.6)
  Top 0.178: PERIPH1_CTL.P$10 27.07,41.17 26.29,40.39 v26.29,39.12 | XCEIVER1_GPIOS.13 20.19,37.47 v20.19,37.69
  Bottom 0.178: v26.29,39.12 26.29,38.35 24.51,36.58 23.5,36.58 22.38,37.69 v20.19,37.69
N$50  (via drill 0.6)
  Top 0.178: PERIPH1_CTL.P$11 27.57,40.4 v27.18,40.01
  Bottom 0.178: v27.18,40.01 27.18,38.74 24.64,36.2 23.24,36.2 23.24,36.22 22.23,37.24 20.96,37.24 20.96,37.21 20.45,36.7 20.07,36.7 19.3,37.47 18.41,37.47 17.78,36.83 17.78,34.8 XCEIVER1_GPIOS.15
N$51  (via drill 0.6)
  Top 0.178: HOST1_CTL.P$26 51.07,42.69 v51.43,43.05
  Bottom 0.178: XCEIVER2_GPIOS.2 58.29,51.56 57.53,50.8 55.24,50.8 52.7,48.26 52.2,48.26 50.93,46.99 50.93,45.97 50.16,45.21 50.16,44.32 v51.43,43.05
N$52  (via drill 0.6)
  Top 0.178: HOST1_CTL.P$27 50.3,43.19 v51.43,44.32 | v53.21,47.24 53.21,48.77 55.75,51.31 XCEIVER2_GPIOS.4
  Bottom 0.178: v53.21,47.24 51.94,47.24 51.43,46.74 v51.43,44.32
N$53
  Top 0.178: HOST1_CTL.P$28 49.66,43.69 51.94,45.97 51.94,48.51 53.21,49.78 XCEIVER2_GPIOS.6
N$54
  Top 0.178: HOST1_CTL.P$29 49.4,44.19 49.4,44.2 49.66,44.2 51.43,45.97 51.43,48.51 50.67,49.28 XCEIVER2_GPIOS.8
N$55
  Top 0.178: HOST1_CTL.P$30 49.64,44.69 50.93,45.97 50.93,48.26 48.13,51.05 XCEIVER2_GPIOS.10
N$56
  Top 0.178: HOST1_CTL.P$31 49.64,45.19 50.42,45.97 50.42,48.01 45.59,52.83 XCEIVER2_GPIOS.12
N$57
  Top 0.178: HOST1_CTL.P$32 49.63,45.69 49.91,45.97 49.91,47.75 45.85,51.82 43.81,51.82 43.05,52.58 XCEIVER2_GPIOS.14
N$58  (via drill 0.6)
  Top 0.178: HOST1_CTL.P$1 48.87,46.71 49.4,47.24 49.4,47.75 45.72,51.44 40.64,51.44 v40.51,51.56
  Bottom 0.178: v40.51,51.56 XCEIVER2_GPIOS.16
N$59  (via drill 0.6)
  Top 0.178: HOST1_CTL.P$4 47.37,47.5 46.35,48.51 v46.35,49.53
  Bottom 0.178: v46.35,49.53 53.47,49.53 57.02,53.09 57.02,54.86 XCEIVER2_GPIOS.1
N$60  (via drill 0.6)
  Top 0.178: HOST1_CTL.P$5 46.87,47.24 46.86,47.24 46.86,47.5 45.34,49.02 v45.34,50.29
  Bottom 0.178: v45.34,50.29 45.59,50.55 52.2,50.55 54.48,52.83 54.48,54.86 XCEIVER2_GPIOS.3
N$61  (via drill 0.6)
  Top 0.178: HOST1_CTL.P$6 46.37,47.49 44.07,49.78 v44.07,50.29
  Bottom 0.178: v44.07,50.29 44.07,50.55 44.83,51.31 51.18,51.31 51.94,52.07 51.94,54.86 XCEIVER2_GPIOS.5
N$62  (via drill 0.6)
  Top 0.178: HOST1_CTL.P$7 45.87,47.22 v42.8,50.29
  Bottom 0.178: v42.8,50.29 42.8,50.55 44.07,51.82 48.39,51.82 49.4,52.83 49.4,54.86 XCEIVER2_GPIOS.7
N$63  (via drill 0.6)
  Top 0.178: HOST1_CTL.P$8 45.37,46.96 43.05,49.28 42.54,49.28 v41.53,50.29
  Bottom 0.178: XCEIVER2_GPIOS.9 46.86,54.86 46.86,52.83 46.35,52.32 44.07,52.32 43.81,52.07 43.31,52.07 v41.53,50.29
N$64  (via drill 0.6)
  Top 0.178: HOST1_CTL.P$9 44.35,45.69 44.32,45.72 44.32,46.23 v40.26,50.29
  Bottom 0.178: XCEIVER2_GPIOS.11 44.2,54.74 44.2,53.09 43.56,52.45 42.54,52.45 40.39,50.29 v40.26,50.29
N$65  (via drill 0.6)
  Top 0.178: HOST1_CTL.P$10 44.09,45.19 v38.99,50.29
  Bottom 0.178: XCEIVER2_GPIOS.13 41.66,54.74 40,54.74 39.37,54.1 39.37,50.67 v38.99,50.29
N$66  (via drill 0.6)
  Top 0.178: HOST1_CTL.P$11 44.8,44.7 43.94,44.7 39.37,49.28 38.79,49.28 v37.77,50.29
  Bottom 0.178: XCEIVER2_GPIOS.15 38.99,54.61 38.99,51.51 v37.77,50.29
N$67  (via drill 0.6)
  Top 0.178: FAULT3.A 39.19,5.76 v38.99,5.97
  Bottom 0.178: R3.1 39.58,6.56 v38.99,5.97
N$68  (via drill 0.6)
  Top 0.178: v44.32,17.53 44.32,17.02 45.59,15.75 45.59,15.24 44.07,13.72 44.07,2.79 43.18,1.91 41.02,1.91 40.64,2.29 40.08,2.29 FAULT3.K
  Bottom 0.178: AP2146_3/4.FLG1 44.32,19.08 v44.32,17.53
N$69  (via drill 0.6)
  Top 0.178: FAULT4.A 48.97,5.51 v48.64,5.84
  Bottom 0.178: v48.64,5.84 49.62,6.82 R4.1
N$70  (via drill 0.6)
  Top 0.178: FAULT4.K 50.37,1.91 53.97,1.91 54.36,2.29 54.36,3.94 54.1,4.19 54.1,5.08 53.72,5.46 53.72,6.6 50.8,9.53 50.8,10.16 50.67,10.29 50.67,12.06 v51.82,13.21
  Bottom 0.178: v51.82,13.21 51.82,14.48 51.31,14.99 51.31,17.4 50.42,18.29 48.51,18.29 48.39,18.16 47.37,18.16 47.24,18.03 45.97,18.03 45.72,18.29 AP2146_3/4.FLG2
N$71  (via drill 0.6)
  Top 0.178: FAULT1.K 19.48,2.03 14.35,2.03 13.46,2.92 13.46,4.7 14.48,5.71 14.48,7.24 15.37,8.13 15.37,14.48 17.14,16.26 17.14,16.76 17.91,17.53 17.91,18.54 18.16,18.8 18.67,18.8 19.18,19.3 19.18,20.57 18.77,20.98 v18.64,20.98
  Bottom 0.178: 15.37,29.24 AP2146_1/2.FLG1 15.24,28.45 15.49,28.19 16.13,28.19 16.51,27.81 16.51,25.78 17.14,25.15 17.14,22.86 17.91,22.1 17.91,21.84 18.64,21.11 v18.64,20.98
N$72  (via drill 0.6)
  Top 0.178: FAULT2.A 30.91,5.51 v31.12,5.71
  Bottom 0.178: v31.12,5.71 29.85,5.71 29.46,6.1 29.46,7.58 R2.1
N$73
  Top 0.178: R1.1 17.06,4.48 18.03,5.46 19.51,5.46 FAULT1.A
N$74  (via drill 0.6)
  Top 0.178: FAULT2.K 29.8,2.16 29.21,2.16 28.96,1.91 24.89,1.91 23.75,3.05 23.75,13.08 22.48,14.35 20.7,14.35 19.81,15.24 19.81,20.7 20.17,21.06 v20.22,21.06
  Bottom 0.178: 16.64,29.24 AP2146_1/2.FLG2 16.51,28.32 16.89,27.94 16.89,25.91 17.78,25.02 18.67,25.02 18.92,24.77 18.92,23.11 20.22,21.82 v20.22,21.06
N$75  (via drill 0.6)
  Top 0.178: PERIPH1_CTL.P$22 32.75,44.69 v33.15,45.09
  Bottom 0.178: v33.15,45.09 33.15,46.1 32.64,46.61 32.13,46.61 31.88,46.86 31.88,47.84 C15.2
N$76
  Top 0.178: HOST1.D+ 24.77,64.52 25.27,64.01 29.08,64.01 29.85,63.25 R9.2
N$77  (via drill 0.6)
  Top 0.178: HOST1.D- 24.12,63.9 v24.26,63.75 | R10.2 19.94,56.9 20.19,57.15 20.32,57.15 v20.7,57.53
  Bottom 0.178: v24.26,63.75 21.46,63.75 20.45,62.74 20.45,57.79 v20.7,57.53
N$78
  Top 0.178: HOST1_CTL.P$20 46.87,40.64 45.85,39.62 45.85,38.52 R12.2
N$79  (via drill 0.6)
  Top 0.178: PERIPH1_OR_HOST4.3 23.5,16.51 23.24,16.76 23.24,20.57 23.75,21.08 32.26,21.08 32.77,21.59 32.77,23.37 33.27,23.88 33.27,24.38 32.51,25.15 32.51,25.78 33.02,26.29 33.02,27.18 33.27,27.43 33.27,28.7 33.66,29.08 34.67,29.08 35.18,29.59 35.18,31.5 36.32,32.64 v36.65,32.64 | R12.1 40.77,38.35 v39.62,37.21
  Bottom 0.178: v39.62,37.21 39.24,36.83 38.99,36.83 38.1,35.94 38.1,33.91 37.72,33.53 37.08,33.53 36.65,33.1 v36.65,32.64
N$84
  Top 0.178: 5V_TOPROC.1 10.79,61.6 9.78,62.61 9.14,62.61 PROC_INTERFACE.1
N$85
  Top 0.178: PROC_INTERFACE.3 8.51,62.23 9.02,61.72 9.02,57.15 9.73,56.44 3.3V_TOPROC.1
N$86  (via drill 0.6)
  Top 0.178: 5V_STATUS.A 18.58,67.06 v20.07,67.06
  Bottom 0.178: v20.07,67.06 20.03,67.09 R13.2
N$87  (via drill 0.6)
  Top 0.178: 3.3V_STATUS.A 19.27,62.45 20.07,63.25 v20.07,63.88
  Bottom 0.178: R14.2 19.47,62.65 20.07,63.25 v20.07,63.88
N$88
  Top 0.178: PERIPH4_STATUS.A 49.91,12.19 50.16,12.45 R18.1
N$89  (via drill 0.6)
  Top 0.178: GND_TOPROC.1 16.38,60.71 15.11,61.98 11.05,61.98 8.64,64.39 v8.64,64.77
  Bottom 0.178: v8.64,64.77 8.64,64.14 8,63.5 4.45,63.5 | 4.45,63.5 PROC_INTERFACE.2 | PROC_INTERFACE.4 4.45,63.5
N$90  (via drill 0.6)
  Top 0.178: PERIPH3_STATUS.A 39.97,7.37 39.24,7.37 38.73,7.87 v38.73,8.89
  Bottom 0.178: v38.73,8.89 36.58,8.89 35.94,9.53 35.94,11.05 35.43,11.56 34.29,11.56 34.07,11.77 R17.1
N$91  (via drill 0.6)
  Top 0.178: v25.78,15.62 25.78,16.89 25.27,17.4 25.27,18.29 25.78,18.8 25.78,19.68 26.29,20.19 28.04,20.19 v28.45,19.79 | v31.12,7.49 29.81,7.49 PERIPH2_STATUS.A
  Bottom 0.178: v31.12,7.49 30.35,8.26 30.35,8.51 29.85,9.02 29.85,11.81 28.57,13.08 28.57,19.66 v28.45,19.79 | 25.65,12.99 R16.1 25.78,13.12 v25.78,15.62
N$92  (via drill 0.6)
  Top 0.178: v17.53,14.73 17.53,13.84 18.41,12.95 18.41,10.41 17.14,9.14 17.14,8.38 17.91,7.62 19.34,7.62 PERIPH1_STATUS.A
  Bottom 0.178: v17.53,14.73 14.35,14.73 14.1,14.99 14.1,15.91 R15.1
N$94
  Bottom 0.178: SPEED_JMPR1.3 30.61,30.86 30.35,30.61 30.35,29.72 29.72,29.08 29.08,29.08 28.7,28.7 28.13,28.7 R19.2
N$95
  Bottom 0.178: R20.2 22.99,31.5 23.75,32.26 25.27,32.26 25.53,32 25.53,31.11 25.78,30.86 SPEED_JMPR1.1
N$96  (via drill 0.6)
  Top 0.178: v56.01,24.13 56.01,28.96 SPEED_JMPR3.2 | TRANS3.13 52.18,22.36 v52.58,21.97
  Bottom 0.178: v56.01,24.13 56.01,23.37 54.61,21.97 v52.58,21.97
N$97  (via drill 0.6)
  Top 0.178: v53.97,35.05 53.97,33.27 54.48,32.77 54.48,32 54.74,31.75 SPEED_JMPR3.3
  Bottom 0.178: R24.2 53.47,35.56 v53.97,35.05
N$98
  Bottom 0.178: R23.2 48.64,34.29 48.89,34.04 48.89,32.26 49.4,31.75 SPEED_JMPR3.1
N$99
  Bottom 0.178: R22.2 42.89,32.09 42.8,32 42.8,31.5 42.54,31.24 42.54,30.73 42.29,30.48 SPEED_JMPR2.3
N$100  (via drill 0.6)
  Top 0.178: 51.18,23.63 TRANS3.15 51.18,22.61 v50.55,21.97
  Bottom 0.178: JP13.1 56.26,22.86 54.99,21.59 53.47,21.59 52.96,21.08 52.2,21.08 51.31,21.97 v50.55,21.97 51.43,22.86 I/O_EN_SNOOP.D
N$101
  Bottom 0.178: SPEED_JMPR2.1 37.21,30.48 37.72,30.99 37.72,31.5 39.92,33.69 R21.2
N$102
  Top 0.178: HOST1_CTL.P$22 47.87,39.13 48.39,38.61 C20.2
OE1  (via drill 0.6)
  Top 0.178: HOST_XVER.9 26.04,26.17 26.04,29.21 25.02,30.23 24.26,30.23 21.59,27.56 14.86,27.56 v14.48,27.18 | v11.3,34.29 v11.3,30.35
  Bottom 0.178: PROC_INTERFACE.25 v11.3,34.29 | v11.3,30.35 v14.48,27.18
OE2  (via drill 0.6)
  Top 0.178: PERIPH_XVER.9 39.74,26.15 40.13,26.54 v40.13,28.45 | v15.75,25.4 15.11,25.4 13.59,26.92 13.59,27.43 14.73,28.57 22.1,28.57 26.54,33.02 34.16,33.02 34.67,33.53 38.73,33.53 40.13,32.13 v40.13,31.88
  Bottom 0.178: PROC_INTERFACE.33 8.25,25.4 9.52,25.4 12.19,22.73 12.19,22.22 12.83,21.59 13.84,21.59 14.1,21.84 14.1,22.22 14.61,22.73 14.61,25.02 14.99,25.4 v15.75,25.4 | v40.13,31.88 v40.13,28.45
OE3  (via drill 0.6)
  Top 0.178: TRANS3.9 54.24,26.15 54.86,25.53 54.86,20.45 55.24,20.07 55.75,20.07 56.13,20.45 56.9,20.45 57.4,19.94 57.4,19.18 56.52,18.29 56.52,17.27 55.75,16.51 54.99,16.51 54.1,15.62 54.1,14.73 54.74,14.1 58.29,14.1 58.67,13.72 58.67,13.08 60.07,11.68 60.07,3.05 58.55,1.52 56.52,1.52 v55.24,2.79 | v46.35,2.31 45.24,2.31 44.45,1.52 39.24,1.52 38.86,1.91 34.67,1.91 v34.04,2.54 | v13.97,11.3 13.97,9.27 12.95,8.26 12.95,7.49 v13.59,6.86
  Bottom 0.178: v13.59,6.86 18.54,1.91 33.4,1.91 v34.04,2.54 | PROC_INTERFACE.41 5.71,12.7 12.57,12.7 v13.97,11.3 | v55.24,2.79 55.12,2.79 54.23,1.91 46.99,1.91 46.58,2.31 v46.35,2.31
PERIPH1_CTL  (via drill 0.6)
  Top 0.178: v5.46,27.94 2.79,27.94 2.16,27.3 2.16,14.1 v2.79,13.46
  Bottom 0.178: AP2146_1/2.EN1 13.18,29.37 12.32,30.23 12.32,30.73 11.81,31.24 10.03,31.24 9.27,30.48 9.27,29.97 7.24,27.94 v5.46,27.94 | v2.79,13.46 4.45,11.81 PROC_INTERFACE.43
PERIPH2_CTL  (via drill 0.6)
  Top 0.178: v20.45,22.86 19.94,23.37 19.43,23.37 17.27,21.21 17.27,17.4 11.94,12.06 v11.94,10.79
  Bottom 0.178: v20.45,22.86 19.43,23.88 19.43,24.89 18.92,25.4 17.91,25.4 17.27,26.04 17.27,26.8 17.91,27.43 17.91,29.24 AP2146_1/2.EN2 | v11.94,10.79 7.62,10.79 PROC_INTERFACE.44
PERIPH3_CTL
  Bottom 0.178: AP2146_3/4.EN1 41.88,19.21 40.77,20.32 40.26,20.32 39.75,20.83 32.89,20.83 32.64,20.57 21.84,20.57 20.7,19.43 20.7,13.97 18.16,11.43 16.13,11.43 12.45,7.75 5.59,7.75 PROC_INTERFACE.45
PERIPH4_CTL
  Bottom 0.178: AP2146_3/4.EN2 46.99,20.19 46.61,20.57 41.15,20.57 40.51,21.21 32.77,21.21 32.51,20.95 21.72,20.95 20.32,19.56 20.32,14.1 18.03,11.81 16,11.81 13.08,8.89 PROC_INTERFACE.46
RCV1  (via drill 0.6)
  Top 0.178: HOST_XVER.2 21.98,25.15 21.72,24.89 19.43,24.89 16.13,21.59 16.13,17.78 12.07,13.72 9.4,13.72 8.38,12.7 3.56,12.7 v2.67,11.81
  Bottom 0.178: PROC_INTERFACE.22 1.78,36.7 1.78,12.7 v2.67,11.81
RCV2  (via drill 0.6)
  Top 0.178: v34.29,25.02 34.42,25.15 PERIPH_XVER.2
  Bottom 0.178: PROC_INTERFACE.30 5.84,30.61 8.38,30.61 9.91,32.13 11.94,32.13 13.21,30.86 21.34,30.86 23.88,33.4 32.77,33.4 33.02,33.15 33.02,25.65 33.66,25.02 v34.29,25.02
RCV3  (via drill 0.6)
  Top 0.178: TRANS3.2 49.4,25.15 48.13,26.42 48.13,29.46 47.12,30.48 44.07,30.48 41.27,33.27 40,33.27 38.99,34.29 34.42,34.29 33.91,33.78 26.29,33.78 21.84,29.34 14.48,29.34 12.07,26.92 12.07,22.1 12.32,21.84 12.32,20.45 v12.19,20.32
  Bottom 0.178: PROC_INTERFACE.38 5.71,20.32 v12.19,20.32
SCLK1  (via drill 0.6)
  Top 0.178: PROC_INTERFACE.10 5.71,53.34 8.38,53.34 9.64,52.08 v9.64,49.96 | PERIPH1_CTL.P$13 28.57,40.9 31.12,38.35 31.62,38.35 v32.26,37.72
  Bottom 0.178: v32.26,37.72 31.62,38.35 31.12,38.35 29.21,40.26 29.21,41.15 27.18,43.18 27.18,45.97 25.15,48.01 25.15,52.83 24.51,53.47 22.86,53.47 22.48,53.85 19.81,53.85 19.18,54.48 18.16,54.48 17.53,53.85 17.53,52.2 14.99,49.66 10.54,49.66 10.29,49.91 9.7,49.91 v9.64,49.96
SCLK2
  Top 0.178: PROC_INTERFACE.13 5.71,50.8 3.43,50.8 2.54,51.69 2.54,69.21 3.68,70.36 38.61,70.36 39.24,69.72 39.24,68.58 40.39,67.44 40.39,65.66 40,65.28 40,63.63 39.75,63.37 39.75,62.36 40,62.1 40,60.96 41.78,59.18 42.67,59.18 43.18,58.67 43.18,57.91 41.78,56.52 41.78,55.63 41.15,54.99 39.88,54.99 39.12,54.23 39.12,52.07 38.61,51.56 37.21,51.56 36.58,50.93 36.58,49.78 37.85,48.51 38.86,48.51 43.68,43.69 HOST1_CTL.P$13
SOFTCON1  (via drill 0.6)
  Top 0.178: HOST_XVER.5 23.76,27.67 23.5,27.94 22.99,27.94 21.34,26.29 19.3,26.29 14.99,21.97 14.99,18.29 11.81,15.11 11.43,15.11 9.52,17.02 9.52,17.91 10.03,18.41 10.03,20.57 9.14,21.46 9.14,23.24 10.16,24.26 10.16,24.77 9.52,25.4 9.14,25.4 8.51,26.04 8.51,27.18 8.38,27.3 8.38,27.69 8.64,27.94 8.64,34.8 8.38,35.05 8.38,35.94 v9.27,36.83
  Bottom 0.178: v9.27,36.83 PROC_INTERFACE.23
SOFTCON2  (via drill 0.6)
  Top 0.178: PERIPH_XVER.5 36.7,26.91 36.08,26.91 35.81,27.18 v35.81,27.81 | v10.03,28.57 10.67,28.57 13.97,31.88 v13.97,32.89
  Bottom 0.178: v13.97,32.89 14.86,32 20.02,32 20.4,32.38 20.4,34.29 20.88,34.77 22.99,34.77 23.14,34.93 27.18,34.93 27.81,35.56 27.81,36.83 27.43,37.21 27.43,37.97 27.81,38.35 28.57,38.35 28.96,37.97 28.96,37.21 28.57,36.83 28.57,35.18 29.21,34.54 33.53,34.54 34.16,33.91 34.16,29.46 v35.81,27.81 | v10.03,28.57 8.89,28.57 PROC_INTERFACE.31
SOFTCON3  (via drill 0.6)
  Top 0.178: TRANS3.5 50.68,27.42 50.42,27.69 49.91,27.69 49.66,27.94 49.66,29.46 47.12,32 44.07,32 41.27,34.8 40,34.8 39.37,35.43 34.04,35.43 33.53,34.93 25.91,34.93 21.46,30.48 14.1,30.48 10.92,27.3 10.92,24 9.91,22.99 9.91,21.84 11.3,20.45 11.3,16.76 v11.43,16.64
  Bottom 0.178: v11.43,16.64 8.38,16.64 8.25,16.51 PROC_INTERFACE.39
SPEED1  (via drill 0.6)
  Top 0.178: HOST_XVER.1 21.98,24.65 21.72,24.38 19.43,24.38 16.51,21.46 16.51,17.65 12.07,13.21 10.79,13.21 10.03,12.45 v10.03,9.91
  Bottom 0.178: PROC_INTERFACE.21 5.71,40.64 2.67,40.64 1.4,39.37 1.4,10.92 2.16,10.16 9.78,10.16 v10.03,9.91
SPEED2  (via drill 0.6)
  Top 0.178: v34.67,23.75 34.67,24.26 35.05,24.64 35.95,24.64 PERIPH_XVER.1
  Bottom 0.178: PROC_INTERFACE.29 8,30.23 8.51,30.23 10.03,31.75 11.81,31.75 13.08,30.48 21.46,30.48 24,33.02 32.26,33.02 32.64,32.64 32.64,25.53 34.42,23.75 v34.67,23.75
SPEED3  (via drill 0.6)
  Top 0.178: TRANS3.1 49.14,24.65 47.62,26.16 47.62,29.46 47.12,29.97 44.07,29.97 41.27,32.77 40,32.77 38.86,33.91 34.54,33.91 34.04,33.4 26.42,33.4 21.97,28.96 14.61,28.96 12.45,26.8 12.45,22.22 12.7,21.97 12.7,21.08 13.08,20.7 13.08,19.94 v12.19,19.05
  Bottom 0.178: PROC_INTERFACE.37 7.62,19.68 11.56,19.68 v12.19,19.05
SUSPEND1  (via drill 0.6)
  Top 0.178: v15.62,26.67 16.13,27.18 21.72,27.18 24.26,29.72 25.02,29.72 25.53,29.21 25.53,27.94 25.27,27.69 25.02,27.69 24.77,27.43 HOST_XVER.7 | v9.27,35.56 9.27,34.67 9.14,34.54 9.14,27.56 v9.27,27.43
  Bottom 0.178: v9.27,27.43 10.29,27.43 12.7,25.02 13.46,25.02 14.22,25.78 14.73,25.78 v15.62,26.67 | v9.27,35.56 5.71,35.56 PROC_INTERFACE.24
SUSPEND2  (via drill 0.6)
  Top 0.178: PERIPH_XVER.7 37.72,27.3 38.23,27.81 38.35,27.81 v38.86,28.32 | v9.65,26.16 10.16,26.67 10.16,27.56 13.84,31.24 14.48,31.24 15.62,32.38 v15.62,32.89
  Bottom 0.178: v9.65,26.16 8.25,26.16 7.49,25.4 5.71,25.4 PROC_INTERFACE.32 | v15.62,32.89 16.13,32.38 19.74,32.38 19.99,32.64 19.99,34.42 20.73,35.15 22.86,35.15 23.01,35.31 27.05,35.31 27.43,35.69 27.43,36.7 27.05,37.08 27.05,38.1 27.69,38.74 28.7,38.74 29.34,38.1 29.34,37.08 28.96,36.7 28.96,35.69 29.34,35.31 34.04,35.31 34.54,34.8 34.54,30.1 35.94,28.7 36.83,28.7 37.34,29.21 37.97,29.21 v38.86,28.32
SUSPEND3  (via drill 0.6)
  Top 0.178: TRANS3.7 51.68,29.21 50.93,29.97 49.66,29.97 47.12,32.51 44.07,32.51 41.27,35.31 40,35.31 39.5,35.81 33.91,35.81 33.4,35.31 25.78,35.31 21.34,30.86 13.97,30.86 10.54,27.43 10.54,24.13 9.52,23.11 9.52,21.59 10.41,20.7 v10.41,17.53
  Bottom 0.178: PROC_INTERFACE.40 5.71,17.78 9.27,17.78 9.52,17.53 v10.41,17.53
VM1  (via drill 0.6)
  Top 0.178: HOST_XVER.4 21.96,26.15 21.72,25.91 19.43,25.91 15.37,21.84 15.37,18.03 12.07,14.73 11.05,14.73 10.16,15.62 v9.65,15.62 | PROC_INTERFACE.20 5.84,40.51 5.84,28.83 6.35,28.32 6.35,27.56 5.71,26.92 5.71,15.62 v6.1,15.24
  Bottom 0.178: v6.1,15.24 9.27,15.24 v9.65,15.62
VM2  (via drill 0.6)
  Top 0.178: PERIPH_XVER.4 35.32,26.15 35.18,26.29 35.18,26.92 v34.54,27.56
  Bottom 0.178: PROC_INTERFACE.28 5.59,32.89 12.32,32.89 13.59,31.62 21.08,31.62 23.62,34.16 33.4,34.16 33.78,33.78 33.78,28.32 v34.54,27.56
VM3  (via drill 0.6)
  Top 0.178: TRANS3.4 49.41,26.15 49.15,26.42 49.15,29.46 47.12,31.5 44.07,31.5 41.27,34.29 40,34.29 39.24,35.05 34.16,35.05 33.66,34.54 26.04,34.54 21.59,30.1 14.22,30.1 11.3,27.18 11.3,23.16 v10.79,22.66
  Bottom 0.178: v10.79,22.66 5.51,22.66 PROC_INTERFACE.36
VP1
  Top 0.178: HOST_XVER.3 21.97,25.65 21.72,25.4 19.43,25.4 15.75,21.72 15.75,17.91 12.07,14.22 9.27,14.22 8.76,14.73 8.76,17.78 8.25,18.29 8.25,24.51 8.13,24.64 8.13,27.05 8,27.18 8,27.81 8.25,28.07 8.25,34.67 8,34.93 8,36.07 8.25,36.32 8.25,40.64 PROC_INTERFACE.19
VP2  (via drill 0.6)
  Top 0.178: PERIPH_XVER.3 34.93,25.65 v34.29,26.29
  Bottom 0.178: PROC_INTERFACE.27 9.02,31.75 9.78,32.51 12.07,32.51 13.34,31.24 21.21,31.24 23.75,33.78 33.15,33.78 33.4,33.53 33.4,27.18 v34.29,26.29
VP3  (via drill 0.6)
  Top 0.178: TRANS3.3 49.41,25.65 48.64,26.42 48.64,29.46 47.12,30.99 44.07,30.99 41.27,33.78 40,33.78 39.12,34.67 34.29,34.67 33.78,34.16 26.16,34.16 21.72,29.72 14.35,29.72 11.68,27.05 11.68,21.84 v11.43,21.59
  Bottom 0.178: PROC_INTERFACE.35 v11.43,21.59
XI1
  Top 0.178: XTAL_12MHZ.P$2 35.94,56.46 35.94,55.12 35.69,54.86 34.42,54.86 34.25,54.7 C17.2 34.16,53 34.16,52.07 33.91,51.82 33.4,51.82 30.62,49.04 PERIPH1_CTL.P$24
XI2
  Top 0.178: XTAL_12MHZ1.P$2 54.83,37.16 C19.2 51.02,38.52 50.16,39.37 50.16,40.89 49.45,41.61 48.89,41.61 HOST1_CTL.P$24
XO1
  Top 0.178: XTAL_12MHZ.P$1 26.8,56.46 26.8,55.12 27.05,54.86 28.32,54.86 28.49,54.7 C16.2 28.57,53 28.57,52.07 28.83,51.82 29.85,51.82 30.07,51.59 PERIPH1_CTL.P$25
XO2
  Top 0.178: XTAL_12MHZ1.P$1 54.83,46.66 C18.2 53.38,45.21 52.96,45.21 52.32,44.58 52.32,42.67 51.84,42.19 HOST1_CTL.P$25

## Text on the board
tPlace: FIXED 3.3V LED BUG FROM REV1.0 | 5V | GND | 3.3V | GND | PERIPH1 | PERIPH2 | PERIPH3 | PERIPH4 | K | 5V | A | K | A | 3.3V | 5V<>CPU | NC | NC | NC | NC | 7<--OUT-->0 | GND<>CPU | 3.3V<>CPU | 7<--IN-->0 | HOST1_CTL_GPIOS | 7<--OUT-->0 | 7<--IN-->0 | 2 | P | PERIPH1_CTL | HOST1_CTL | PERIPH1_CTL_GPIOS | SPEED CTL | SPEED CTL | SPEED CTL | FULL | LOW | FULL | LOW | FULL | LOW | PERIPH2_XCEIVER | CPU | CPU | CPU | ON | ON | ON | HOST2_XCEIVER | SNOOP(3)_XCEIVER | VccI/O Override | VccI/O Override | P4 | D+ | H1 | P4 | D+ | H2 | VccI/O Override | L | D+ | P | PERIPH4 | HOST2 | LOOPBACK | HOST/PERIPH 4 | P4 | D- | H1 | P4 | D- | H2 | PASSTHRU | HOST1_CTL_OUT | XCEIVER2_OUT | L | P | K | K | K | A | HOST2 | A | A | A | HOST3 | K | HOST4 | HOST1 | Pat Pannuto | Eric Wustrow | USB Exp R1.0 -- 8/16/2011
